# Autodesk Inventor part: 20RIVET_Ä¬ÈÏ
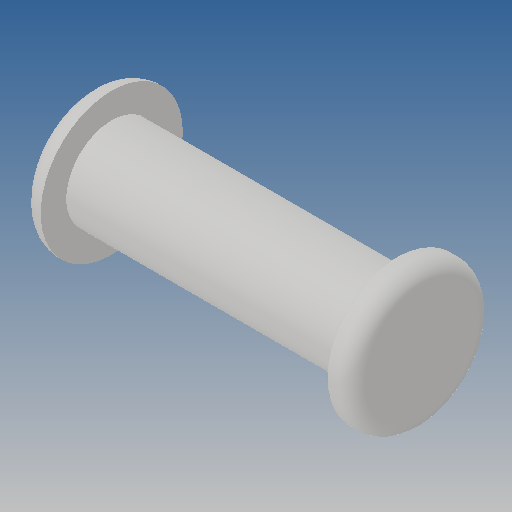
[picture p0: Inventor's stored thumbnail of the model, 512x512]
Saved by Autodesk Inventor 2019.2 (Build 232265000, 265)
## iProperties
Created: 2010-06
Part Number: 20RIVET_Ä¬ÈÏ
Material: Ogólny
Document SubType Name: Modeling
Designer: CADENGINEERING4
Density: 1 g/cm^3
Appearance: Domyślna
Author: CADENGINEERING4
Revision Number: ÈÎºÎ
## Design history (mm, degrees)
feature "NONE"
node "Bryła1"
